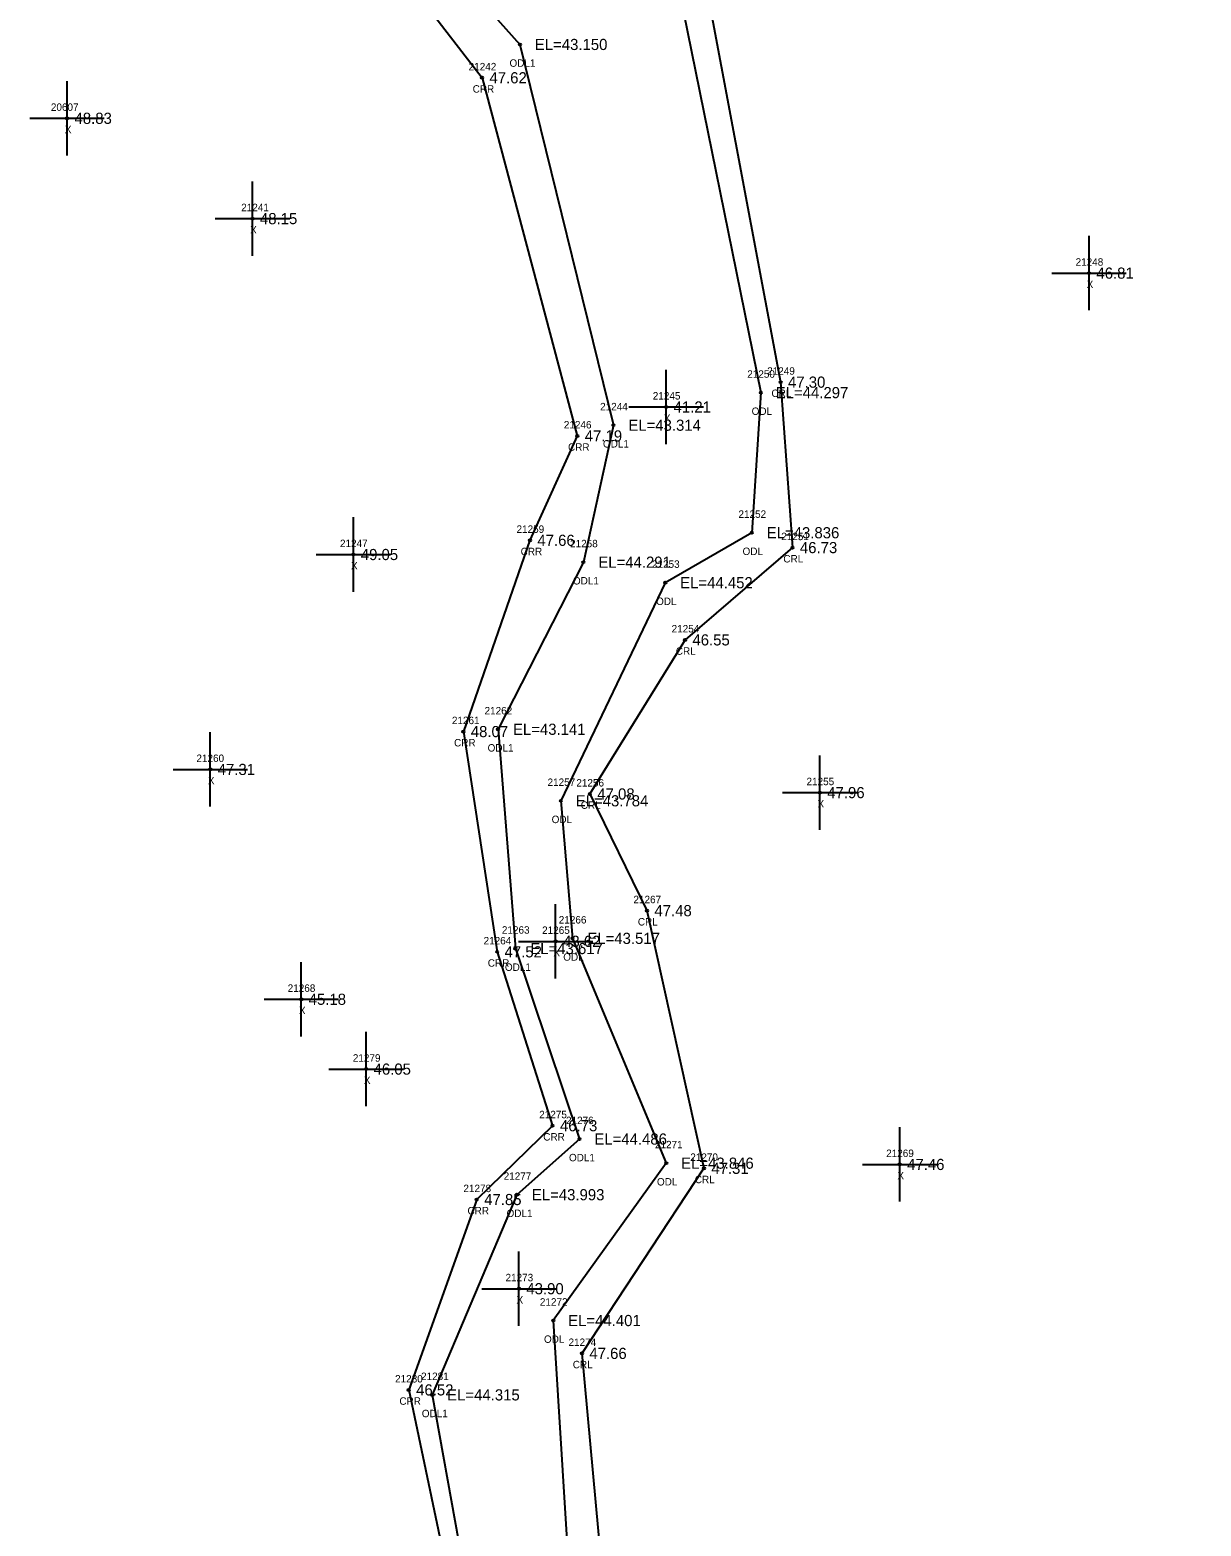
# Model space of a CAD drawing. Extents: x 2420351 to 2422725, y 845330 to 846558.
# Drawn here: x 2421757.8 to 2421915.3, y 845531.3 to 845732.5 of the extents above; entities that cross this region are included whole.
import ezdxf

# ---------------------------------------------------------------- set-up
doc = ezdxf.new("R2010")
doc.units = 0
for name, color, linetype in [('RD_EX_H2O', 7, 'Continuous'), ('RD_EX_H2O_txCode', 7, 'Continuous'), ('RD_EX_Misc', 7, 'Continuous'), ('RD_EX_Misc_txCode', 7, 'Continuous'), ('RD_EX_TX_H2O_ELEV', 7, 'Continuous'), ('RD_EX_TX_Misc_ELEV', 7, 'Continuous'), ('RD_SMD_Locator', 7, 'Continuous')]:
    doc.layers.add(name, color=color, linetype=linetype)

msp = doc.modelspace()

# ---------------------------------------------------------------- linework, layer by layer
at = {"layer": 'RD_EX_H2O'}
for points in [[(2421789.64, 845837.83), (2421802.06, 845811.15), (2421810.66, 845784.93), (2421844.56, 845740.42), (2421856.1, 845683.72), (2421854.89, 845664.88), (2421843.25, 845658.16), (2421829.21, 845628.83), (2421830.77, 845610.33), (2421843.38, 845580.1), (2421828.19, 845558.94), (2421831.91, 845499.14), (2421809.98, 845486.71), (2421808.79, 845466.96), (2421839.47, 845434.68), (2421874.6, 845421.86), (2421897.47, 845382.52), (2421913.19, 845366.87)], [(2421810.77, 845819.82), (2421810.76, 845810.56), (2421816.9, 845792.5), (2421822.4, 845786.03), (2421848.72, 845738.63), (2421858.75, 845685.13), (2421860.35, 845662.88), (2421845.9, 845650.47), (2421833.11, 845629.75), (2421840.79, 845614.06), (2421848.44, 845579.41), (2421832.04, 845554.52), (2421837.19, 845498.45), (2421811.62, 845484.13), (2421811.72, 845469.11), (2421841.99, 845438.03), (2421875.97, 845424.56), (2421900.41, 845383.13), (2421915.29, 845367.51)], [(2421769.97, 845784.59), (2421775.7, 845782.12), (2421786.73, 845771.94), (2421823.71, 845730.54), (2421836.28, 845679.34), (2421832.24, 845660.92), (2421820.77, 845638.45), (2421823.1, 845608.96), (2421831.71, 845583.35), (2421823.31, 845575.86), (2421811.92, 845548.94), (2421818.99, 845509.7), (2421790.81, 845485.52), (2421791.34, 845474.13), (2421803.96, 845452.08), (2421836.18, 845421.02), (2421870.76, 845406.66), (2421878.5, 845385.15), (2421867.47, 845378.72), (2421847.36, 845376.11), (2421845.3, 845344.22)], [(2421768.08, 845778.29), (2421776.13, 845776.03), (2421785.06, 845769.58), (2421818.61, 845726.06), (2421831.42, 845677.9), (2421825.05, 845663.86), (2421816.1, 845638.14), (2421820.64, 845608.52), (2421828.09, 845585.14), (2421817.9, 845575.21), (2421808.75, 845549.61), (2421816.7, 845511.81), (2421785.75, 845489.97), (2421789.04, 845473.23), (2421801.09, 845449.66), (2421834.75, 845418.44), (2421870.95, 845402.12), (2421876.24, 845387.07), (2421866.97, 845385.32), (2421844.91, 845376.57), (2421842.84, 845344.63)]]:
    msp.add_lwpolyline(points, dxfattribs=at)
at = {"layer": 'RD_EX_Misc'}
for p, q in [((2421762.82, 845715.61), (2421762.82, 845725.61)), ((2421757.82, 845720.61), (2421767.82, 845720.61)), ((2421787.75, 845702.12), (2421787.75, 845712.12)), ((2421782.75, 845707.12), (2421792.75, 845707.12)), ((2421900.22, 845694.79), (2421900.22, 845704.79)), ((2421895.22, 845699.79), (2421905.22, 845699.79)), ((2421843.37, 845676.79), (2421843.37, 845686.79)), ((2421838.37, 845681.79), (2421848.37, 845681.79)), ((2421801.31, 845656.95), (2421801.31, 845666.95)), ((2421796.31, 845661.95), (2421806.31, 845661.95)), ((2421782.07, 845628.05), (2421782.07, 845638.05)), ((2421864.03, 845624.93), (2421864.03, 845634.93)), ((2421777.07, 845633.05), (2421787.07, 845633.05)), ((2421859.03, 845629.93), (2421869.03, 845629.93)), ((2421828.51, 845604.93), (2421828.51, 845614.93)), ((2421823.51, 845609.93), (2421833.51, 845609.93)), ((2421794.3, 845597.14), (2421794.3, 845607.14)), ((2421789.3, 845602.14), (2421799.3, 845602.14)), ((2421803.03, 845587.75), (2421803.03, 845597.75)), ((2421798.03, 845592.75), (2421808.03, 845592.75)), ((2421874.77, 845574.93), (2421874.77, 845584.93)), ((2421869.77, 845579.93), (2421879.77, 845579.93)), ((2421823.57, 845558.22), (2421823.57, 845568.22)), ((2421818.57, 845563.22), (2421828.57, 845563.22))]:
    msp.add_line(p, q, dxfattribs=at)
at = {"layer": 'RD_SMD_Locator'}
for centre in [(2421823.71, 845730.54), (2421818.61, 845726.06), (2421762.82, 845720.61), (2421787.75, 845707.12), (2421900.22, 845699.79), (2421858.75, 845685.13), (2421856.1, 845683.72), (2421843.37, 845681.79), (2421836.28, 845679.34), (2421831.42, 845677.9), (2421854.89, 845664.88), (2421825.05, 845663.86), (2421860.35, 845662.88), (2421801.31, 845661.95), (2421832.24, 845660.92), (2421843.25, 845658.16), (2421845.9, 845650.47), (2421816.1, 845638.14), (2421820.77, 845638.45), (2421782.07, 845633.05), (2421864.03, 845629.93), (2421829.21, 845628.83), (2421833.11, 845629.75), (2421840.79, 845614.06), (2421828.51, 845609.93), (2421830.77, 845610.33), (2421820.64, 845608.52), (2421823.1, 845608.96), (2421794.3, 845602.14), (2421803.03, 845592.75), (2421828.09, 845585.14), (2421831.71, 845583.35), (2421843.38, 845580.1), (2421874.77, 845579.93), (2421848.44, 845579.41), (2421823.31, 845575.86), (2421817.9, 845575.21), (2421823.57, 845563.22), (2421828.19, 845558.94), (2421832.04, 845554.52), (2421808.75, 845549.61), (2421811.92, 845548.94)]:
    msp.add_circle(centre, 0.15, dxfattribs=at)

# ---------------------------------------------------------------- texts
at = {"layer": 'RD_EX_H2O_txCode'}
for s, p in [('21242', (2421816.81, 845727.06)), ('ODL1', (2421822.3, 845727.54)), ('CRR', (2421817.35, 845724.06)), ('21250', (2421854.27, 845685.72)), ('21249', (2421856.95, 845686.13)), ('21244', (2421834.49, 845681.34)), ('CRL', (2421857.52, 845683.13)), ('ODL', (2421854.86, 845680.72)), ('21246', (2421829.61, 845678.9)), ('CRR', (2421830.17, 845675.9)), ('ODL1', (2421834.87, 845676.34)), ('21252', (2421853.09, 845666.88)), ('21259', (2421823.25, 845664.86)), ('21251', (2421858.84, 845663.88)), ('CRR', (2421823.8, 845661.86)), ('21258', (2421830.45, 845662.92)), ('ODL', (2421853.64, 845661.88)), ('21253', (2421841.46, 845660.16)), ('CRL', (2421859.12, 845660.88)), ('ODL1', (2421830.83, 845657.92)), ('ODL', (2421842.01, 845655.16)), ('21254', (2421844.1, 845651.47)), ('CRL', (2421844.67, 845648.47)), ('21261', (2421814.56, 845639.14)), ('21262', (2421818.95, 845640.45)), ('CRR', (2421814.85, 845636.14)), ('ODL1', (2421819.36, 845635.45)), ('21257', (2421827.42, 845630.83)), ('21256', (2421831.29, 845630.75)), ('CRL', (2421831.88, 845627.75)), ('ODL', (2421827.97, 845625.83)), ('21267', (2421838.97, 845615.06)), ('21263', (2421821.28, 845610.96)), ('21266', (2421828.93, 845612.33)), ('CRL', (2421839.56, 845612.06)), ('21264', (2421818.82, 845609.52)), ('ODL', (2421829.53, 845607.33)), ('CRR', (2421819.38, 845606.52)), ('ODL1', (2421821.69, 845605.96)), ('21275', (2421826.3, 845586.14)), ('21276', (2421829.9, 845585.35)), ('CRR', (2421826.84, 845583.14)), ('21271', (2421841.86, 845582.1)), ('ODL1', (2421830.3, 845580.35)), ('21270', (2421846.61, 845580.41)), ('21277', (2421821.52, 845577.86)), ('ODL', (2421842.13, 845577.1)), ('CRL', (2421847.22, 845577.41)), ('21278', (2421816.11, 845576.21)), ('CRR', (2421816.65, 845573.21)), ('ODL1', (2421821.91, 845572.86)), ('21272', (2421826.39, 845560.94)), ('ODL', (2421826.94, 845555.94)), ('21274', (2421830.24, 845555.52)), ('CRL', (2421830.81, 845552.52)), ('21280', (2421806.92, 845550.61)), ('21281', (2421810.41, 845550.94)), ('CRR', (2421807.5, 845547.61)), ('ODL1', (2421810.51, 845545.94))]:
    msp.add_text(s, height=1, dxfattribs=at).set_placement(p)
at = {"layer": 'RD_EX_Misc_txCode'}
for s, p in [('20607', (2421760.64, 845721.61)), ('X', (2421762.51, 845718.61)), ('21241', (2421786.23, 845708.12)), ('X', (2421787.43, 845705.12)), ('21248', (2421898.42, 845700.79)), ('X', (2421899.91, 845697.79)), ('21245', (2421841.57, 845682.79)), ('X', (2421843.05, 845679.79)), ('21247', (2421799.51, 845662.95)), ('X', (2421800.99, 845659.95)), ('21260', (2421780.21, 845634.05)), ('X', (2421781.75, 845631.05)), ('21255', (2421862.24, 845630.93)), ('X', (2421863.72, 845627.93)), ('21265', (2421826.69, 845610.93)), ('X', (2421828.2, 845607.93)), ('21268', (2421792.48, 845603.14)), ('X', (2421793.99, 845600.14)), ('21279', (2421801.24, 845593.75)), ('X', (2421802.72, 845590.75)), ('21269', (2421872.95, 845580.93)), ('X', (2421874.46, 845577.93)), ('21273', (2421821.77, 845564.22)), ('X', (2421823.25, 845561.22))]:
    msp.add_text(s, height=1, dxfattribs=at).set_placement(p)
at = {"layer": 'RD_EX_TX_H2O_ELEV'}
for s, p in [('EL=43.150', (2421825.71, 845729.79)), ('47.62', (2421819.61, 845725.31)), ('EL=44.297', (2421858.1, 845682.97)), ('47.30', (2421859.75, 845684.38)), ('47.19', (2421832.42, 845677.15)), ('EL=43.314', (2421838.28, 845678.59)), ('47.66', (2421826.05, 845663.11)), ('EL=43.836', (2421856.89, 845664.13)), ('46.73', (2421861.35, 845662.13)), ('EL=44.291', (2421834.24, 845660.17)), ('EL=44.452', (2421845.25, 845657.41)), ('46.55', (2421846.9, 845649.72)), ('48.07', (2421817.1, 845637.39)), ('EL=43.141', (2421822.77, 845637.7)), ('47.08', (2421834.11, 845629)), ('EL=43.784', (2421831.21, 845628.08)), ('47.48', (2421841.79, 845613.31)), ('EL=43.517', (2421832.77, 845609.58)), ('47.52', (2421821.64, 845607.77)), ('EL=43.617', (2421825.1, 845608.21)), ('46.73', (2421829.09, 845584.39)), ('EL=44.486', (2421833.71, 845582.6)), ('EL=43.846', (2421845.38, 845579.35)), ('47.31', (2421849.44, 845578.66)), ('47.85', (2421818.9, 845574.46)), ('EL=43.993', (2421825.31, 845575.11)), ('EL=44.401', (2421830.19, 845558.19)), ('47.66', (2421833.04, 845553.77)), ('46.52', (2421809.75, 845548.86)), ('EL=44.315', (2421813.92, 845548.19))]:
    msp.add_text(s, height=1.5, dxfattribs=at).set_placement(p)
at = {"layer": 'RD_EX_TX_Misc_ELEV'}
for s, p in [('48.83', (2421763.82, 845719.86)), ('48.15', (2421788.75, 845706.37)), ('46.81', (2421901.22, 845699.04)), ('41.21', (2421844.37, 845681.04)), ('49.05', (2421802.31, 845661.2)), ('47.31', (2421783.07, 845632.3)), ('47.96', (2421865.03, 845629.18)), ('43.62', (2421829.51, 845609.18)), ('45.18', (2421795.3, 845601.39)), ('46.05', (2421804.03, 845592)), ('47.46', (2421875.77, 845579.18)), ('43.90', (2421824.57, 845562.47))]:
    msp.add_text(s, height=1.5, dxfattribs=at).set_placement(p)

doc.saveas('drawing.dxf')
